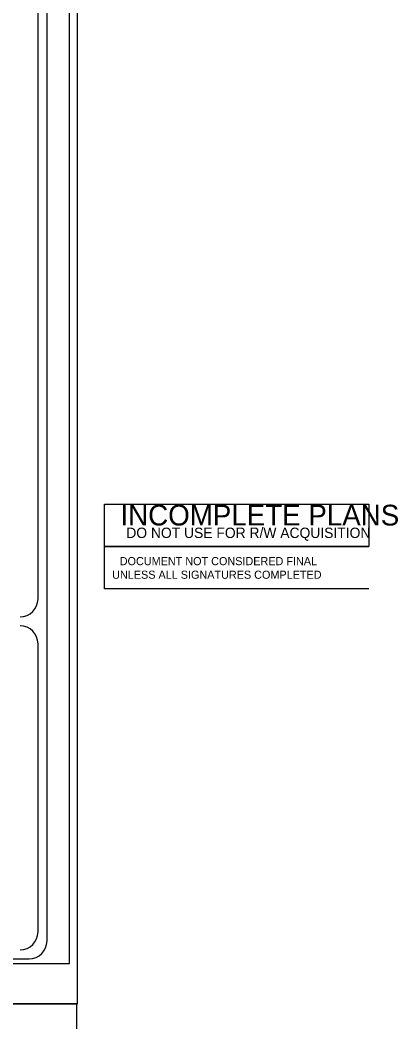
# Model space of a CAD drawing. Extents: x 925297 to 940193, y 663541 to 689899.
# Drawn here: x 938513 to 940193, y 681019 to 685471 of the extents above; entities that cross this region are included whole.
import ezdxf

# ---------------------------------------------------------------- set-up
doc = ezdxf.new("R2010")
doc.units = 0
for name, color, linetype in [('Sheet Cutting Line CELL', 7, 'Continuous'), ('Sheet Plot Border Inside CELL', 7, 'Continuous'), ('Sheet Plot Border Outside CELL', 7, 'Continuous'), ('Sheet Sticker Exception Certification CELL', 7, 'Continuous'), ('Sheet Sticker Incomplete CELL', 7, 'Continuous'), ('Sheet Title CELL', 7, 'Continuous')]:
    doc.layers.add(name, color=color, linetype=linetype)

msp = doc.modelspace()

# ---------------------------------------------------------------- linework, layer by layer
at = {"layer": 'Sheet Cutting Line CELL'}
msp.add_line((925296.7, 681098.7), (938768.7, 681098.7), dxfattribs=at)
at = {"layer": 'Sheet Plot Border Inside CELL'}
msp.add_lwpolyline([(925400.7, 681278.2), (938732.7, 681278.2), (938732.7, 689719), (925400.7, 689719)], close=True, dxfattribs=at)
at = {"layer": 'Sheet Plot Border Outside CELL'}
for points in [[(938768.7, 689898.6), (925296.7, 689898.6), (925296.7, 681098.7), (938768.7, 681098.7)], [(925296.7, 672338.7), (938764.7, 672338.7), (938764.7, 681098.7), (925296.7, 681098.7)]]:
    msp.add_lwpolyline(points, close=True, dxfattribs=at)
at = {"layer": 'Sheet Sticker Exception Certification CELL'}
for p, q in [((938887.7, 682943.4), (938887.7, 683131.4)), ((938887.7, 683131.4), (940063.7, 683131.4)), ((940063.7, 682943.4), (938887.7, 682943.4))]:
    msp.add_line(p, q, dxfattribs=at)
at = {"layer": 'Sheet Sticker Incomplete CELL'}
msp.add_lwpolyline([(938887.7, 683131.4), (938887.7, 683319.4), (940063.7, 683319.4), (940063.7, 683131.4)], close=True, dxfattribs=at)
at = {"layer": 'Sheet Title CELL'}
for points in [[(938632.7, 681378.7), (938632.7, 689618.6)], [(938592.7, 682898.6), (938592.7, 689578.7)], [(938592.7, 681418.7), (938592.7, 682698.7)], [(926712.7, 681298.6), (938552.7, 681298.6)]]:
    msp.add_lwpolyline(points, dxfattribs=at)
for centre, start, end in [((938512.7, 682899.1), 270, 360), ((938512.7, 682699.1), 0, 90), ((938512.7, 681419.1), 270, 360), ((938552.7, 681379.1), 270, 360)]:
    msp.add_arc(centre, 80, start, end, dxfattribs=at)

# ---------------------------------------------------------------- texts
at = {"layer": 'Sheet Sticker Exception Certification CELL'}
for s, p in [('DOCUMENT NOT CONSIDERED FINAL', (938956.1, 683048.7)), ('UNLESS ALL SIGNATURES COMPLETED', (938922.4, 682988.3))]:
    msp.add_text(s, height=36, dxfattribs=at).set_placement(p)
at = {"layer": 'Sheet Sticker Incomplete CELL'}
for s, height, p in [('INCOMPLETE PLANS', 92.16, (938959.3, 683225)), ('DO NOT USE FOR R/W ACQUISITION', 46.08, (938985.3, 683169.4))]:
    msp.add_text(s, height=height, dxfattribs=at).set_placement(p)

doc.saveas('drawing.dxf')
